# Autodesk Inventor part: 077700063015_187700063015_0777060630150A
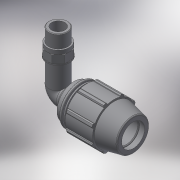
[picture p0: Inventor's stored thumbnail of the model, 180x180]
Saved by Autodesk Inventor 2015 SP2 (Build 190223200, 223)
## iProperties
Created: 2017-02
Part Number: 077700063015_187700063015_0777060630150A
Material: Generic
Description: PLASSON 90° ELBOW MALE WITH INTEGRAL BRASS THREAD 63-1.1/2"
Document SubType Name: Modeling
Designer: KIM
Mass: 174.249 g
Surface Area: 431.906 cm^2
Volume: 174.249 cm^3
Density: 1 g/cm^3
Appearance: Default
Author: KIM
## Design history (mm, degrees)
derived "07770.ipt"
feature "Solid1::07770.ipt"
tag "TaggingFeature1"
body "Solid1"
other parameters: "d2" = 63, "d4" = 14, "d5" = 42, "d7" = 113, "d9" = 24, "d11" = 5.6, "d13" = 120 deg, "d14" = 81.9, "d15" = 12 deg, "d16" = 98.31, "d18" = 3.15, "d19" = 35 deg, "d20" = 17.5 deg, "d21" = 105.09, "d23" = 0, "d25" = 360 deg, "d27" = 2.26, "d33" = 1.26, "d42" = 62.16, "d43" = 3.39, "d46" = 1.89, "d51" = 168, "d68" = 11.2, "d72" = 126, "d73" = 47.803, "d74" = 22, "d75" = 54.97345, "d76" = 33.4621, "d79" = 19.1212, "d80" = 1.43409, "d83" = 0, "d84" = 0, "d91" = 84.75, "d94" = 47.803, "d95" = 33.4621, "d96" = 11.2, "d97" = 50 deg, "d98" = 2.8, "d99" = 95.3607, "d100" = 2.8, "d101" = 2.8, "d105" = 2.2, "d106" = 57.3636, "d107" = 22, "d108" = 13.2, "d109" = 0, "d_" = 63, "E_" = 113, "A_" = 168, "l_2" = 22, "A_1" = 126, "R_" = 47.803
